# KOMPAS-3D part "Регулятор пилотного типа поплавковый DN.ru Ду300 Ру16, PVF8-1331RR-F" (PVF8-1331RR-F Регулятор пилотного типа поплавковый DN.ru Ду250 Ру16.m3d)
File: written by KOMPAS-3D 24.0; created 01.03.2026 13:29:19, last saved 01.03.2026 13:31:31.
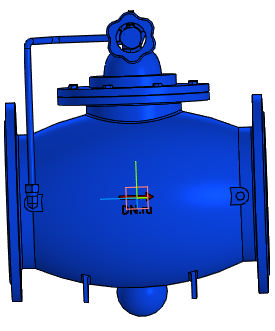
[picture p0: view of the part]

Document properties: Автор: R2D2; Полное имя файла: E:\Работа\Зайцев\PVF8-1331RR-F Регулятор пилотного типа поплавковый DN.ru Ду15-300\DN300\PVF8-1331RR-F Регулятор пилотного типа поплавковый DN.ru Ду250 Ру16.m3d

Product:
- Part/product: Регулятор пилотного типа поплавковый DN.ru Ду300 Ру16  | designation PVF8-1331RR-F
    Масса: 130
    Раздел спецификации: Прочие изделия
    Примечание: D230-10616
    additional columns: D230-10616

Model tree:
1. Операция без истории:1

Expressions: PVF8-1331RR-F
